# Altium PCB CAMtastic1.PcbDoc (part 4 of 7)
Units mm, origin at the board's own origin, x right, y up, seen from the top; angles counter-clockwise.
Board outline 150.22 x 135.24 mm, 5 copper layers (Top Layer, Layer 1, Mid-Layer 1, Layer 2, Bottom Layer), stack 0.461 mm thick; 0 components, 362 nets, 2885 pads, 0 vias.
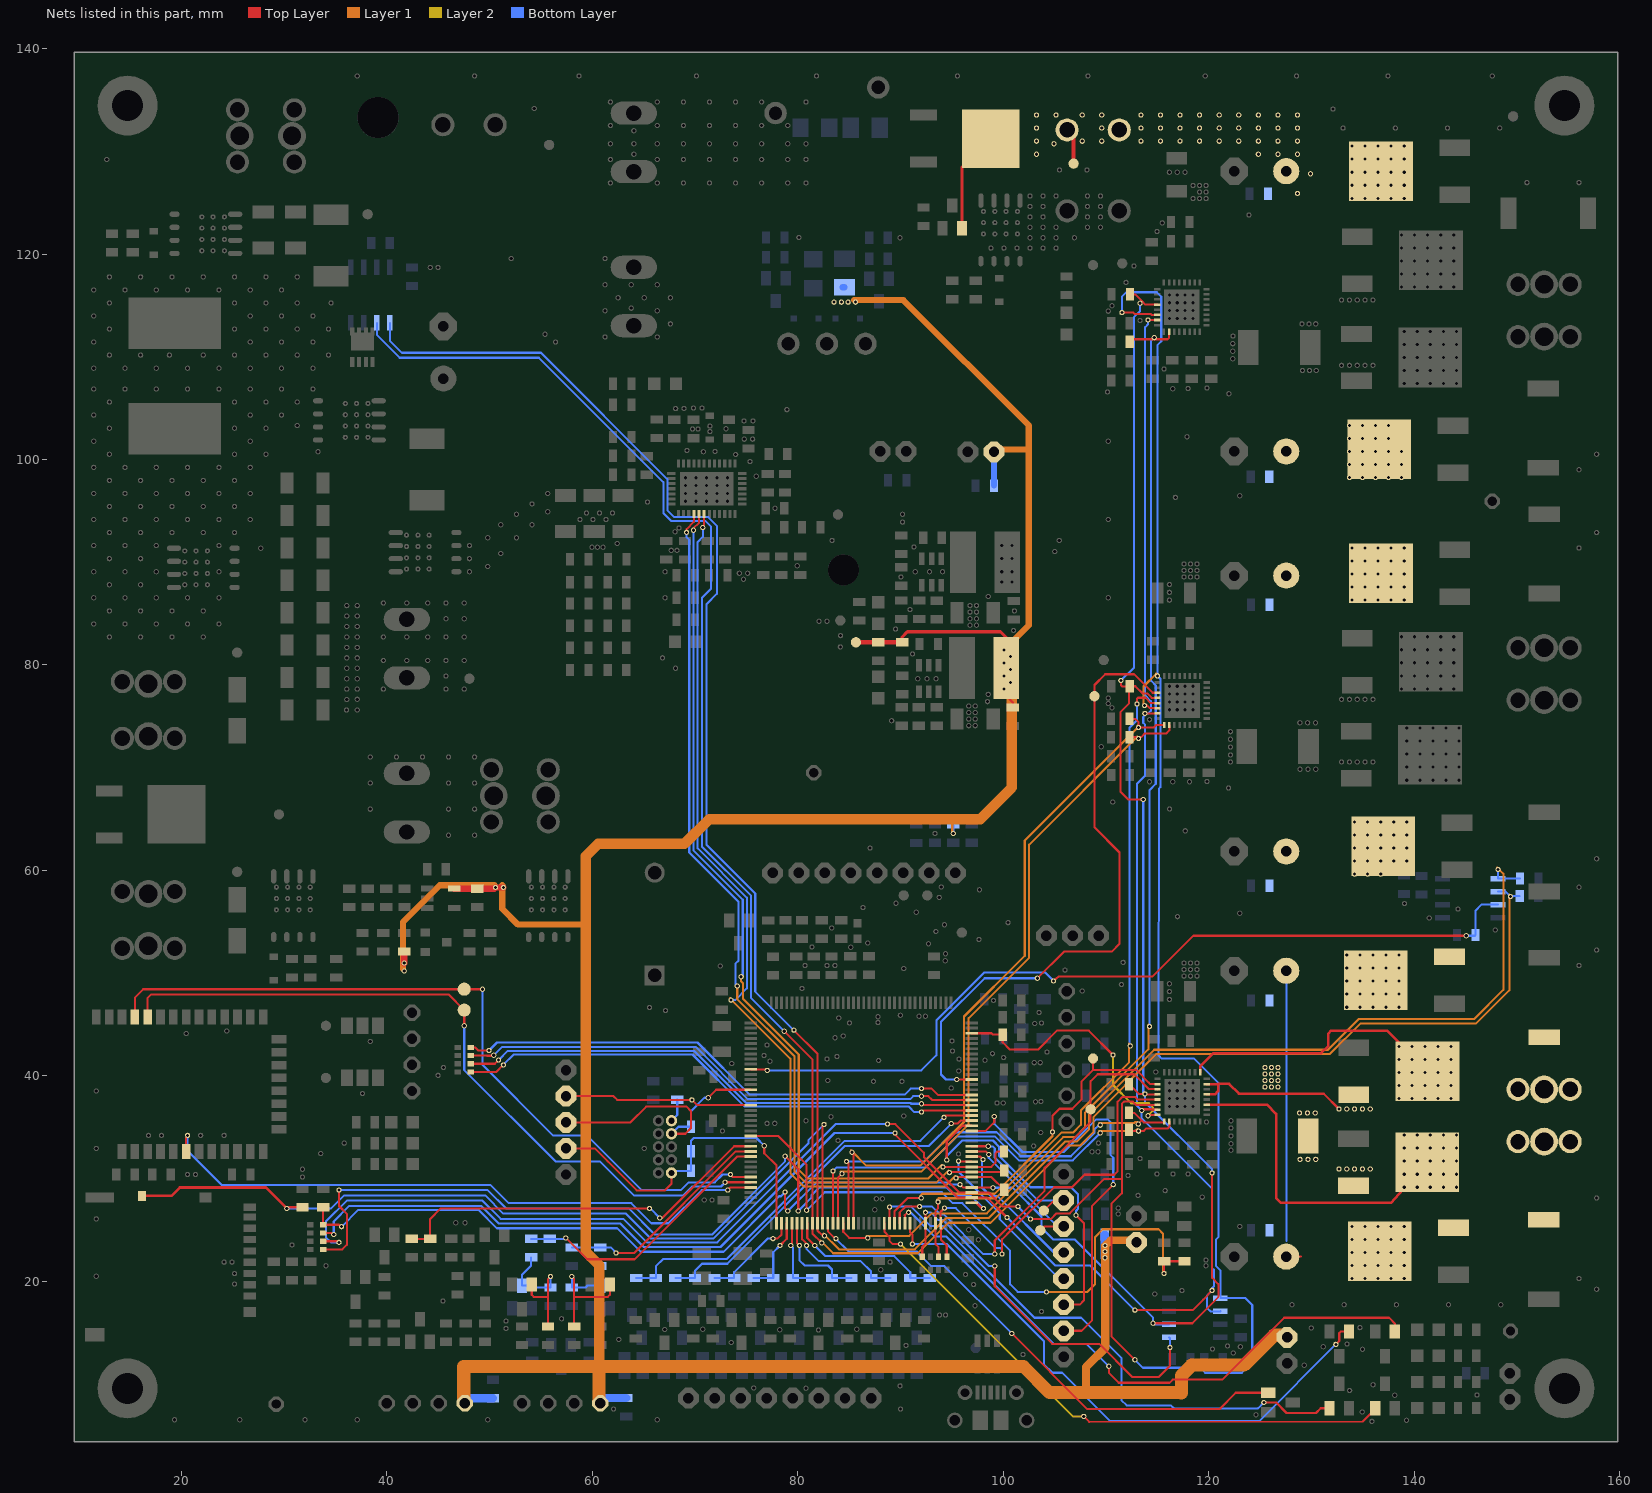
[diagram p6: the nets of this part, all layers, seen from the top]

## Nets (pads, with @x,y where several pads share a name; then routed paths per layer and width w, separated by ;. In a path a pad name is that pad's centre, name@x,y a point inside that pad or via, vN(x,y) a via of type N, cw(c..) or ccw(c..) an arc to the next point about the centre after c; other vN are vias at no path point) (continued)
$Net7: pad.1@119.805,37.203 pad.1@139.018,29.159 pad.1@139.018,30.429 pad.1@139.018,31.699 pad.1@139.018,32.969 pad.1@139.018,34.239 pad.1@140.288,29.159 pad.1@140.288,30.429 pad.1@140.288,31.699 pad.1@140.288,32.969 pad.1@140.288,34.239 pad.1@141.273,31.603 pad.1@141.558,29.159 pad.1@141.558,30.429 pad.1@141.558,31.699 pad.1@141.558,32.969 pad.1@141.558,34.239 pad.1@142.828,29.159 pad.1@142.828,30.429 pad.1@142.828,31.699 pad.1@142.828,32.969 pad.1@142.828,34.239 pad.1@143.821,25.216 pad.1@144.098,29.159 pad.1@144.098,30.429 pad.1@144.098,31.699 pad.1@144.098,32.969 pad.1@144.098,34.239 pad.1@150.093,33.604 pad.1@152.584,25.994 pad.1@152.633,33.604 pad.1@155.173,33.604 | length 32
  Top Layer w0.254: pad.1@119.805,37.203 125.64,37.203 126.547,36.297 126.547,28.092 127.004,27.635 137.748,27.635 pad.1@141.273,31.603
$Net8: pad.1@119.155,40.353 pad.1@138.51,37.795 pad.1@138.51,39.065 pad.1@138.51,40.335 pad.1@138.51,41.605 pad.1@138.51,42.875 pad.1@139.78,37.795 pad.1@139.78,39.065 pad.1@139.78,40.335 pad.1@139.78,41.605 pad.1@139.78,42.875 pad.1@141.05,37.795 pad.1@141.05,39.065 pad.1@141.05,40.335 pad.1@141.05,41.605 pad.1@141.05,42.875 pad.1@141.294,40.468 pad.1@142.32,37.795 pad.1@142.32,39.065 pad.1@142.32,40.335 pad.1@142.32,41.605 pad.1@142.32,42.875 pad.1@143.59,37.795 pad.1@143.59,39.065 pad.1@143.59,40.335 pad.1@143.59,41.605 pad.1@143.59,42.875 pad.1@143.435,51.606 pad.1@150.093,38.684 pad.1@152.633,38.684 pad.1@152.635,43.765 pad.1@155.173,38.684 | length 26.5
  Top Layer w0.254: pad.1@119.155,40.353 119.155,40.891 120.479,42.215 130.941,42.215 131.627,42.901 131.627,44.12 131.906,44.399 137.362,44.399 pad.1@141.294,40.468 pad.1@141.304,40.479
$Net9: pad.1@119.805,38.203 pad.1@119.805,39.203 pad.1@128.833,36.398 pad.1@128.884,31.877 pad.1@129.595,36.398 pad.1@129.646,31.877 pad.1@129.676,34.169 pad.1@130.357,36.398 pad.1@130.408,31.877 pad.1@132.668,30.937 pad.1@132.668,36.779 pad.1@133.43,30.937 pad.1@133.43,36.779 pad.1@134.093,29.318 pad.1@134.114,38.183 pad.1@134.192,30.937 pad.1@134.192,36.779 pad.1@134.954,30.937 pad.1@134.954,36.779 pad.1@135.716,30.937 pad.1@135.716,36.779 | length 15.8
  Top Layer w0.203: 131.17,38.278 pad.1@132.668,36.779
  Top Layer w0.254: pad.1@119.805,38.203 120.608,38.203 120.911,38.506 120.911,39.218 121.975,39.218 122.915,38.278 131.17,38.278 ; pad.1@119.805,39.203 120.896,39.203
  Top Layer w0.305: 120.896,39.203 120.911,39.218
$Net10: pad.1@95.967,122.522 pad.1@98.772,131.242 pad.1@103.23,129.718 pad.1@103.23,130.988 pad.1@103.23,132.258 pad.1@103.23,133.528 pad.1@104.923,130.734 pad.1@105.135,133.528 pad.1@106.201,132.08 pad.1@106.839,128.803 pad.1@107.675,130.988 pad.1@107.675,133.528 pad.1@109.58,130.988 pad.1@109.58,132.258 pad.1@109.58,133.528 pad.1@111.281,132.08 pad.1@113.39,130.988 pad.1@113.39,132.258 pad.1@113.39,133.528 pad.1@115.295,130.988 pad.1@115.295,132.258 pad.1@115.295,133.528 pad.1@117.2,130.988 pad.1@117.2,132.258 pad.1@117.2,133.528 pad.1@119.105,130.988 pad.1@119.105,132.258 pad.1@119.105,133.528 pad.1@121.01,130.988 pad.1@121.01,132.258 pad.1@121.01,133.528 pad.1@122.915,130.988 pad.1@122.915,132.258 pad.1@122.915,133.528 pad.1@124.82,129.718 pad.1@124.82,130.988 pad.1@124.82,132.258 pad.1@124.82,133.528 pad.1@125.77,125.882 pad.1@125.455,38.913 pad.1@125.455,39.548 pad.1@125.455,40.183 pad.1@125.455,40.818 pad.1@125.872,98.323 pad.1@125.897,24.968 pad.1@125.897,47.346 pad.1@125.897,58.496 pad.1@125.897,85.877 pad.1@126.09,38.913 pad.1@126.09,39.548 pad.1@126.09,40.183 pad.1@126.09,40.818 pad.1@126.725,38.913 pad.1@126.725,39.548 pad.1@126.725,40.183 pad.1@126.725,40.818 pad.1@126.725,129.718 pad.1@126.725,130.988 pad.1@126.725,132.258 pad.1@126.725,133.528 pad.1@127.54,22.403 pad.1@127.54,50.241 pad.1@127.54,61.849 pad.1@127.54,88.697 pad.1@127.54,100.787 pad.1@127.54,128.067 pad.1@128.63,125.908 pad.1@128.63,129.718 pad.1@128.63,130.988 pad.1@128.63,132.258 pad.1@128.63,133.528 pad.1@129.9,127.813 pad.1@133.43,46.685 pad.1@133.43,47.955 pad.1@133.43,49.225 pad.1@133.43,50.495 pad.1@133.43,51.765 pad.1@133.684,98.247 pad.1@133.684,99.517 pad.1@133.684,100.787 pad.1@133.684,102.057 pad.1@133.684,103.327 pad.1@133.938,20.269 pad.1@133.938,21.539 pad.1@133.938,22.809 pad.1@133.938,24.079 pad.1@133.938,25.349 pad.1@133.938,86.309 pad.1@133.938,87.579 pad.1@133.938,88.849 pad.1@133.938,90.119 pad.1@133.938,91.389 pad.1@133.938,125.425 pad.1@133.938,126.695 pad.1@133.938,127.965 pad.1@133.938,129.235 pad.1@133.938,130.505 pad.1@134.7,46.685 pad.1@134.7,47.955 pad.1@134.7,49.225 pad.1@134.7,50.495 pad.1@134.7,51.765 pad.1@134.192,59.639 pad.1@134.192,60.909 pad.1@134.192,62.179 pad.1@134.192,63.449 pad.1@134.192,64.719 pad.1@134.954,98.247 pad.1@134.954,99.517 pad.1@134.954,100.787 pad.1@134.954,102.057 pad.1@134.954,103.327 pad.1@135.97,46.685 pad.1@135.97,47.955 pad.1@135.97,49.225 pad.1@135.97,50.495 pad.1@135.97,51.765 pad.1@135.208,20.269 pad.1@135.208,21.539 pad.1@135.208,22.809 pad.1@135.208,24.079 pad.1@135.208,25.349 pad.1@135.208,86.309 pad.1@135.208,87.579 pad.1@135.208,88.849 pad.1@135.208,90.119 pad.1@135.208,91.389 pad.1@135.208,125.425 pad.1@135.208,126.695 pad.1@135.208,127.965 pad.1@135.208,129.235 pad.1@135.208,130.505 pad.1@135.462,59.639 pad.1@135.462,60.909 pad.1@135.462,62.179 pad.1@135.462,63.449 pad.1@135.462,64.719 pad.1@136.224,98.247 pad.1@136.224,99.517 pad.1@136.224,100.787 pad.1@136.224,102.057 pad.1@136.224,103.327 pad.1@136.255,49.321 pad.1@136.478,20.269 pad.1@136.478,21.539 pad.1@136.478,22.809 pad.1@136.478,24.079 pad.1@136.478,25.349 pad.1@136.478,86.309 pad.1@136.478,87.579 pad.1@136.478,88.849 pad.1@136.478,90.119 pad.1@136.478,91.389 pad.1@136.478,125.425 pad.1@136.478,126.695 pad.1@136.478,127.965 pad.1@136.478,129.235 pad.1@136.478,130.505 pad.1@136.591,100.99 pad.1@136.641,22.931 pad.1@136.732,59.639 pad.1@136.732,60.909 pad.1@136.732,62.179 pad.1@136.732,63.449 pad.1@136.732,64.719 pad.1@136.763,88.913 pad.1@136.763,128.067 pad.1@136.972,62.345 pad.1@137.24,46.685 pad.1@137.24,47.955 pad.1@137.24,49.225 pad.1@137.24,50.495 pad.1@137.24,51.765 pad.1@137.494,98.247 pad.1@137.494,99.517 pad.1@137.494,100.787 pad.1@137.494,102.057 pad.1@137.494,103.327 pad.1@137.748,20.269 pad.1@137.748,21.539 pad.1@137.748,22.809 pad.1@137.748,24.079 pad.1@137.748,25.349 pad.1@137.748,86.309 pad.1@137.748,87.579 pad.1@137.748,88.849 pad.1@137.748,90.119 pad.1@137.748,91.389 pad.1@137.748,125.425 pad.1@137.748,126.695 pad.1@137.748,127.965 pad.1@137.748,129.235 pad.1@137.748,130.505 pad.1@138.002,60.909 pad.1@138.002,62.179 pad.1@138.002,63.449 pad.1@138.002,64.719 pad.1@138.51,46.685 pad.1@138.51,47.955 pad.1@138.51,49.225 pad.1@138.51,50.495 pad.1@138.51,51.765 pad.1@138.764,98.247 pad.1@138.764,99.517 pad.1@138.764,100.787 pad.1@139.018,20.269 pad.1@139.018,21.539 pad.1@139.018,22.809 pad.1@139.018,24.079 pad.1@139.018,25.349 pad.1@139.018,86.309 pad.1@139.018,87.579 pad.1@139.018,88.849 pad.1@139.018,90.119 pad.1@139.018,91.389 pad.1@139.018,125.425 pad.1@139.018,126.695 pad.1@139.018,127.965 pad.1@139.018,129.235 pad.1@139.018,130.505 pad.1@139.272,60.909 pad.1@139.272,62.179 pad.1@139.272,63.449 pad.1@139.272,64.719 | length 41.2
  Top Layer w0.203: pad.1@127.54,22.403 128.982,22.423
  Top Layer w0.305: pad.1@95.967,122.522 95.967,128.402 98.772,131.208 pad.1@98.772,131.242
  Top Layer w0.406: pad.1@106.201,132.08 106.839,131.442 pad.1@106.839,128.803
  Bottom Layer w0.203: pad.1@127.54,50.241 127.56,50.221 127.56,23.947
$Net11: pad.1@90.911,25.654 pad.1@91.139,23.622 pad.1@132.363,13.868 pad.1@133.646,15.119 | length 57.1
  Top Layer w0.203: pad.1@90.911,25.654 90.911,25.603 90.911,24.79 91.139,24.562 pad.1@91.139,23.622 ; pad.1@132.363,13.868 132.694,14.199 132.694,14.961 132.852,15.119 pad.1@133.646,15.119
  Bottom Layer w0.203: pad.1@91.139,23.622 94.517,23.622 103.941,14.199 103.941,11.938 104.779,11.1 105.719,11.1 110.418,6.401 124.896,6.401 pad.1@132.363,13.868
$Net12: pad.1@88.911,25.654 pad.1@88.929,27.229 pad.1@125.353,8.204 pad.1@131.746,7.639 | length 56
  Top Layer w0.203: pad.1@88.911,25.654 88.929,25.756 pad.1@88.929,27.229 ; pad.1@125.353,8.204 126.547,8.204 127.563,7.188 130.433,7.188 130.89,7.645 131.74,7.645 pad.1@131.746,7.639 131.595,7.639 131.576,7.62 pad.1@131.601,7.62
  Bottom Layer w0.203: pad.1@88.929,27.229 88.98,27.28 91.038,27.28 92.943,25.375 94.111,25.375 103.026,16.459 107.573,16.459 111.485,12.548 111.485,8.433 111.993,7.925 116.311,7.925 116.615,7.62 124.794,7.645 pad.1@125.353,8.204
$Net13: pad.1@92.098,22.393 pad.1@92.409,26.721 pad.1@92.411,25.654 pad.1@99.166,21.488 pad.1@116.124,14.554 pad.1@116.209,13.564 | length 39.3
  Top Layer w0.203: pad.1@92.098,22.393 92.104,22.399 92.104,23.343 92.411,23.649 pad.1@92.411,25.654 92.411,26.595 pad.1@92.409,26.721 ; pad.1@99.166,21.488 99.166,19.507 104.754,13.919 109.326,13.919 112.551,10.693 115.142,10.693 116.209,11.76 pad.1@116.209,13.564
  Bottom Layer w0.203: pad.1@92.409,26.721 92.917,26.721 93.679,25.959 94.136,25.959 98.607,21.488 pad.1@99.166,21.488 ; pad.1@116.124,14.554 116.209,14.478 pad.1@116.209,13.564
$Net14: pad.1@33.783,25.508 pad.1@33.783,27.218 pad.1@35.581,25.324 pad.1@78.761,28.694 pad.1@79.015,26.848 pad.1@95.787,29.413 pad.1@96.905,29.148 pad.1@98.988,29.108 pad.1@111.434,78.486 pad.1@112.235,39.198 pad.1@112.311,77.914 pad.1@112.336,116.078 pad.1@113.313,115.214 pad.1@113.618,66.904 pad.1@113.771,38.252 pad.1@114.98,115.083 pad.1@114.575,15.926 pad.1@115.005,38.203 pad.1@115.005,76.792 pad.1@116.124,15.824 pad.1@120.324,30.556 | length 219
  Top Layer w0.203: pad.1@33.783,27.218 pad.1@33.783,25.508 35.314,25.508 35.498,25.324 pad.1@35.581,25.324 ; pad.1@78.761,28.694 78.761,27.102 pad.1@79.015,26.848 ; pad.1@95.787,29.413 96.052,29.148 pad.1@96.905,29.148 98.948,29.148 pad.1@98.988,29.108 ; pad.1@111.434,78.486 111.434,78.054 111.586,77.902 pad.1@112.29,77.902 ; pad.1@112.235,39.198 112.247,39.167 113.161,38.252 pad.1@113.771,38.252 113.821,38.202 pad.1@115.005,38.203 ; pad.1@112.336,116.078 112.831,116.078 113.504,115.405 ; pad.1@113.313,115.214 113.504,115.405 ; pad.1@113.618,66.904 112.145,66.904 111.408,67.64 111.408,75.438 112.247,76.276 112.247,77.876 pad.1@112.29,77.902 ; pad.1@114.575,15.926 118.385,15.926 120.925,18.466 120.925,19.736 120.324,20.337 pad.1@120.324,30.556 ; pad.1@114.98,115.083 113.826,115.083 113.504,115.405 ; pad.1@115.005,76.792 114.448,76.792 113.999,77.241 113.542,77.241 112.856,77.927 112.324,77.927 pad.1@112.311,77.914 pad.1@112.29,77.902
  Bottom Layer w0.203: pad.1@35.581,25.324 37.22,26.963 48.904,26.963 50.696,25.171 62.403,25.171 64.689,22.885 72.766,22.885 78.164,28.284 78.35,28.284 pad.1@78.761,28.694 ; pad.1@79.015,26.848 81.783,29.616 94.619,29.616 94.822,29.413 pad.1@95.787,29.413 ; pad.1@98.988,29.108 100.918,29.108 103.712,26.314 103.712,25.222 104.855,24.079 106.963,24.079 114.575,16.468 pad.1@114.575,15.926 114.657,15.926 114.759,15.824 pad.1@116.124,15.824 ; pad.1@111.434,78.486 112.704,79.705 112.704,113.843 113.313,114.452 pad.1@113.313,115.214 ; pad.1@113.618,66.904 113.618,38.405 pad.1@113.771,38.252 113.771,37.465 120.324,30.912 pad.1@120.324,30.556
$Net15: pad.1@75.417,34.148 pad.1@80.852,26.924 pad.1@104.195,18.974 pad.1@115.65,20.777 pad.1@115.65,21.96 pad.1@117.631,21.96 | length 64.6
  Top Layer w0.203: pad.1@75.417,34.148 78.073,34.148 80.852,31.369 pad.1@80.852,26.924 ; pad.1@115.65,20.777 pad.1@115.65,21.96 pad.1@117.631,21.96
  Layer 1 w0.203: pad.1@104.195,18.974 104.203,18.982 108.186,18.982 108.914,19.71 108.914,24.308 109.676,25.07 115.112,25.07 115.544,24.638 pad.1@115.544,20.98
  Bottom Layer w0.203: pad.1@80.852,26.924 82.605,28.677 94.009,28.677 95.076,27.61 96.016,27.61 100.664,22.962 100.664,19.71 101.401,18.974 pad.1@104.195,18.974
$Net16: pad.1@33.783,24.708 pad.1@34.819,24.562 pad.1@89.463,34.442 pad.1@96.905,28.148 pad.1@100.359,26.213 pad.1@112.797,17.196 pad.1@113.466,36.627 pad.1@113.771,75.286 pad.1@114.075,113.589 pad.1@114.98,113.583 pad.1@115.005,36.703 pad.1@115.005,75.292 pad.1@120.324,19.126 pad.1@121.125,17.094 | length 208.8
  Top Layer w0.203: pad.1@33.783,24.708 34.59,24.708 34.736,24.562 pad.1@34.819,24.562 ; pad.1@89.463,34.442 89.463,34.265 95.579,28.148 pad.1@96.905,28.148 98.424,28.148 pad.1@100.359,26.213 ; pad.1@112.797,17.196 118.432,17.196 119.46,18.224 pad.1@120.324,19.126 ; pad.1@113.466,36.627 113.593,36.754 114.431,36.754 114.482,36.703 pad.1@115.005,36.703 ; pad.1@113.771,75.286 114.99,75.286 pad.1@115.005,75.292 ; pad.1@114.075,113.589 114.081,113.583 pad.1@114.98,113.583
  Bottom Layer w0.203: pad.1@34.819,24.562 34.819,25.832 36.343,27.356 49.158,27.356 50.885,25.629 62.708,25.629 64.994,23.343 72.461,23.343 83.561,34.442 pad.1@89.463,34.442 ; pad.1@100.359,26.213 100.385,26.213 105.058,21.539 108.453,21.539 pad.1@112.797,17.196 ; pad.1@114.075,113.589 114.075,113.157 113.796,112.878 113.796,77.038 114.355,76.479 114.355,75.54 114.101,75.286 pad.1@113.771,75.286 113.771,75.108 113.618,74.955 113.618,74.371 113.771,74.219 113.771,69.19 113.009,68.428 113.009,37.084 pad.1@113.466,36.627 113.466,35.865 120.324,29.007 120.324,21.285 120.502,21.107 120.502,19.533 120.324,19.355 pad.1@120.324,19.126 119.841,18.644 119.841,17.399 120.171,17.069 121.086,17.069 pad.1@121.125,17.094
$Net17: pad.1@96.905,34.648 pad.1@99.115,36.043 pad.1@105.871,15.189 pad.1@110.697,29.413 | length 41.1
  Top Layer w0.203: pad.1@96.905,34.648 98.279,34.648 99.115,35.484 pad.1@99.115,36.043 ; pad.1@105.871,15.189 107.624,15.189 108.64,16.205 108.64,27.356 pad.1@110.697,29.413
  Bottom Layer w0.203: pad.1@99.115,36.043 99.115,35.331 101.858,32.588 105.871,32.588 109.046,35.763 110.164,35.763 110.418,35.509 110.418,32.309 110.697,32.029 pad.1@110.697,29.413
$Net18: pad.1@94.492,31.801 pad.1@96.905,35.148 pad.1@105.871,17.729 pad.1@107.065,26.441 | length 34.2
  Top Layer w0.203: pad.1@94.492,31.801 94.492,33.604 96.036,35.148 pad.1@96.905,35.148 ; pad.1@105.871,17.729 107.421,17.729 107.852,18.161 107.852,25.654 pad.1@107.065,26.441
  Bottom Layer w0.203: pad.1@94.492,31.801 94.492,32.207 95.991,33.706 98.988,33.706 99.572,33.122 99.572,32.233 102.645,29.159 106.582,29.159 107.268,28.473 107.268,27.051 107.065,26.848 pad.1@107.065,26.441
$Net19: pad.1@41.677,50.216 pad.1@41.677,50.978 pad.1@41.677,52.11 pad.1@46.539,58.228 pad.1@47.578,8.136 pad.1@48.789,58.228 pad.1@50.321,8.625 pad.1@50.567,58.344 pad.1@51.329,58.344 pad.1@60.761,8.136 pad.1@63.301,8.647 pad.1@83.519,115.316 pad.1@84.23,115.316 pad.1@84.535,116.761 pad.1@84.891,115.316 pad.1@85.602,115.316 pad.1@85.653,82.207 pad.1@87.837,82.205 pad.1@90.149,82.205 pad.1@95.127,63.602 pad.1@95.127,64.502 pad.1@99.088,97.46 pad.1@99.088,100.754 pad.1@100.055,77.648 pad.1@100.055,78.918 pad.1@100.055,80.188 pad.1@100.055,81.458 pad.1@100.69,78.283 pad.1@100.69,79.553 pad.1@100.69,80.823 pad.1@100.274,79.705 pad.1@100.918,75.855 pad.1@109.873,24.562 pad.1@109.884,22.301 pad.1@109.884,22.911 pad.1@109.884,23.495 pad.1@112.958,23.8 pad.1@127.616,14.554 | length 336.9
  Top Layer w0.203: pad.1@100.274,79.705 100.274,78.918 100.274,76.997 100.918,76.352 pad.1@100.918,75.855
  Top Layer w0.305: pad.1@90.149,82.205 90.149,82.728 90.657,83.236 99.724,83.236 100.283,82.677 100.283,80.823 100.283,79.715 pad.1@100.274,79.705
  Top Layer w0.406: pad.1@85.653,82.207 87.835,82.207 pad.1@87.837,82.205 pad.1@90.149,82.205
  Top Layer w0.61: pad.1@41.677,50.978 pad.1@41.677,52.11 ; pad.1@46.539,58.228 pad.1@48.789,58.228 50.45,58.228 pad.1@50.567,58.344 pad.1@51.329,58.344
  Layer 1 w0.203: 93.852,64.999 95.021,65.126 95.021,64.999 pad.1@95.021,63.805 ; pad.1@99.948,77.851 100.075,77.724 pad.1@100.294,77.724
  Layer 1 w0.61: pad.1@41.57,50.419 41.57,54.991 45.126,58.547 pad.1@50.46,58.547 ; pad.1@51.222,58.547 51.222,56.261 52.746,54.737 59.334,54.737 ; pad.1@85.496,115.519 90.262,115.519 102.463,103.318 102.463,100.965 ; pad.1@98.982,100.957 98.99,100.965 102.463,100.965 ; pad.1@100.583,81.026 100.583,81.982 102.463,83.861 102.463,100.965
  Layer 1 w0.762: pad.1@109.931,23.494 110.44,24.003 pad.1@112.851,24.003
  Layer 1 w0.813: 108.051,9.169 108.051,11.659 109.931,13.539 109.931,22.911 pad.1@109.931,23.494
  Layer 1 w1.016: 60.654,11.709 60.654,21.565 59.334,22.885 59.334,54.737 59.334,61.366 60.578,62.611 68.96,62.611 71.348,64.999 93.852,64.999 95.021,64.999 97.764,64.999 100.837,68.072 100.837,77.181 pad.1@100.294,77.724
  Layer 1 w1.27: pad.1@47.472,8.339 47.472,11.709 60.654,11.709 ; pad.1@60.654,8.339 60.654,11.709 ; 100.29,81.57 100.294,80.823 100.294,78.918 pad.1@100.294,77.724 ; pad.1@127.51,14.757 126.364,14.757 123.443,11.836 118.338,11.836 117.322,10.82 117.322,9.141 117.299,9.119 117.248,9.169 108.051,9.169 104.495,9.169 101.955,11.709 60.654,11.709
  Bottom Layer w0.203: pad.1@95.127,63.602 pad.1@95.127,64.502 ; pad.1@95.127,64.502 95.127,64.516 95.025,64.618 pad.1@95.127,64.502
  Bottom Layer w0.61: pad.1@84.335,116.761 pad.1@84.535,116.761 ; pad.1@99.088,97.46 pad.1@99.088,100.754
  Bottom Layer w0.813: pad.1@47.578,8.136 47.589,8.625 pad.1@50.321,8.625 ; pad.1@60.761,8.136 60.772,8.647 pad.1@63.301,8.647 ; pad.1@109.873,24.562 109.873,23.481 pad.1@109.884,22.911 pad.1@109.884,22.301
$Net21: pad.1@90.411,25.654 pad.1@90.784,26.721 pad.1@110.265,11.735 pad.1@138.091,15.119 | length 59.6
  Top Layer w0.203: pad.1@90.411,25.654 90.411,26.221 90.403,26.441 90.682,26.721 pad.1@90.784,26.721 ; pad.1@110.265,11.735 110.265,11.1 111.231,10.135 116.184,10.135 116.488,10.439 121.314,10.439 127.334,16.459 137.545,16.459 138.104,15.9 138.104,15.132 pad.1@138.091,15.119 pad.1@138.002,15.24
  Bottom Layer w0.203: pad.1@90.784,26.721 90.961,26.721 93.273,24.384 94.416,24.384 104.881,13.919 108.081,13.919 pad.1@110.265,11.735
$Net22: pad.1@88.411,25.654 pad.1@89.996,23.622 pad.1@107.827,6.858 pad.1@136.191,7.639 | length 57.1
  Top Layer w0.203: pad.1@88.411,25.654 88.411,24.852 88.904,24.359 88.904,23.952 89.234,23.622 pad.1@89.996,23.622 ; pad.1@107.827,6.858 108.36,6.325 134.954,6.35 136.173,7.569 136.173,7.62 136.191,7.638 pad.1@136.191,7.639
  Layer 2 w0.203: pad.1@89.996,23.622 106.786,6.833 107.802,6.833 pad.1@107.827,6.858
$Net23: pad.1@83.411,25.654 pad.1@83.418,30.734 pad.1@109.427,34.442 pad.1@112.235,34.773 pad.1@113.161,34.62 pad.1@116.155,35.553 | length 43
  Top Layer w0.203: pad.1@83.411,25.654 83.418,25.661 pad.1@83.418,30.734 ; pad.1@112.235,34.773 112.387,34.62 pad.1@113.161,34.62 113.644,34.62 113.923,34.9 116.006,34.9 116.155,35.049 pad.1@116.155,35.553
  Layer 1 w0.203: pad.1@109.321,34.646 112.75,34.646 pad.1@113.055,34.823
  Bottom Layer w0.203: pad.1@83.418,30.734 83.773,31.09 92.46,31.09 95.483,34.112 99.166,34.112 101.502,31.775 106.76,31.775 pad.1@109.427,34.442
$Net24: pad.1@84.738,31.674 pad.1@84.911,25.654 pad.1@109.427,35.204 pad.1@112.235,36.398 pad.1@113.132,35.302 pad.1@115.655,35.553 | length 42.5
  Top Layer w0.203: pad.1@84.738,31.674 84.911,31.552 pad.1@84.911,25.654 ; pad.1@112.235,36.398 112.755,36.398 113.479,35.674 ; pad.1@113.132,35.302 113.132,35.328 113.479,35.674 ; pad.1@115.655,35.553 115.655,35.507 115.632,35.484 113.669,35.484 113.479,35.674
  Layer 1 w0.203: pad.1@109.321,35.408 112.75,35.408 112.862,35.52 113.011,35.52 pad.1@113.025,35.506
  Bottom Layer w0.203: pad.1@84.738,31.674 92.282,31.674 95.127,34.519 99.343,34.519 101.68,32.182 106.557,32.182 108.868,34.493 108.868,34.798 109.275,35.204 pad.1@109.427,35.204
$Net25: pad.1@96.905,44.148 pad.1@99.942,44.018 pad.1@110.672,42.037 pad.1@114.075,36.119 pad.1@115.005,36.203 | length 26.3
  Top Layer w0.203: pad.1@96.905,44.148 98.858,44.148 98.988,44.018 pad.1@99.942,44.018 99.942,43.267 100.639,42.57 103.382,42.57 105.211,44.399 108.31,44.399 pad.1@110.672,42.037 ; pad.1@114.075,36.119 114.16,36.203 pad.1@115.005,36.203
  Layer 2 w0.203: pad.1@110.672,42.037 110.672,39.116 112.45,37.338 114.152,37.338 114.558,36.932 114.558,36.601 pad.1@114.075,36.119
$Net27: pad.1@89.411,25.654 pad.1@92.003,28.118 pad.1@104.779,34.544 pad.1@108.729,41.694 pad.1@115.005,39.203 | length 36.4
  Top Layer w0.203: pad.1@89.411,25.654 89.411,26.847 90.682,28.118 pad.1@92.003,28.118 ; pad.1@104.779,34.544 104.779,36.119 105.465,36.805 106.709,36.805 107.624,37.719 107.624,39.472 108.741,40.589 ; pad.1@108.729,41.694 108.741,41.681 108.741,40.589 ; pad.1@115.005,39.203 114.279,39.218 114.152,39.345 112.932,40.589 108.741,40.589
  Layer 1 w0.203: pad.1@91.896,28.321 92.1,28.524 99.148,28.524 104.779,34.156 pad.1@104.779,34.544
$Net28: pad.1@82.911,25.654 pad.1@83.697,24.155 pad.1@100.817,14.935 pad.1@125.781,9.154 | length 51.5
  Top Layer w0.203: pad.1@82.911,25.654 82.911,24.865 83.621,24.155 pad.1@83.697,24.155 ; pad.1@100.817,14.935 108.183,7.569 121.035,7.569 122.62,9.154 pad.1@125.781,9.154
  Bottom Layer w0.203: pad.1@83.697,24.155 84.942,22.911 91.546,22.911 92.968,21.488 94.263,21.488 pad.1@100.817,14.935
$Net29: pad.1@89.911,25.654 pad.1@91.85,27.28 pad.1@99.166,22.657 pad.1@108.5,36.754 pad.1@115.005,38.703 | length 40.8
  Top Layer w0.203: pad.1@89.911,25.654 89.911,26.712 90.479,27.28 pad.1@91.85,27.28 ; pad.1@99.166,22.657 99.166,23.978 104.017,28.829 104.017,31.064 108.5,35.547 pad.1@108.5,36.754 ; pad.1@108.284,36.754 pad.1@108.5,36.754 ; pad.1@115.005,38.703 114.999,38.71 114.177,38.71 112.729,40.157 109.173,40.157 108.5,39.484 pad.1@108.5,36.754
  Bottom Layer w0.203: pad.1@91.85,27.28 93.07,27.28 93.832,26.518 94.187,26.518 98.048,22.657 pad.1@99.166,22.657
$Net30: pad.1@93.911,25.654 pad.1@94.263,27.127 pad.1@94.498,22.393 pad.1@99.877,22.657 pad.1@115.005,37.703 | length 39.2
  Top Layer w0.203: pad.1@94.263,27.127 93.886,26.749 pad.1@93.911,25.654 93.911,24.076 94.492,23.495 94.492,22.399 pad.1@94.498,22.393 ; pad.1@99.877,22.657 99.877,24.102 100.73,24.955 104.957,29.159 106.684,29.159 107.903,30.378 110.799,30.378 111.129,30.709 111.129,37.49 111.586,37.948 112.831,37.948 113.085,37.694 114.996,37.694 pad.1@115.005,37.703
  Bottom Layer w0.203: pad.1@94.263,27.127 95.381,27.127 99.267,23.241 99.724,23.241 99.877,23.089 pad.1@99.877,22.657
$Net31: pad.1@33.783,23.108 pad.1@35.327,28.88 pad.1@78.761,32.182 pad.1@80.031,26.848 pad.1@96.905,27.648 pad.1@98.065,27.102 | length 84
  Top Layer w0.203: pad.1@33.783,23.108 35.651,23.108 36.089,23.546 36.089,26.574 35.327,27.336 pad.1@35.327,28.88 ; pad.1@78.761,32.182 80.031,30.912 pad.1@80.031,26.848
  Top Layer w0.254: pad.1@96.905,27.648 97.375,27.648 97.921,27.102 pad.1@98.065,27.102
  Bottom Layer w0.203: pad.1@35.327,28.88 49.805,28.88 51.583,27.102 63.521,27.102 66.061,24.562 71.649,24.562 78.761,31.674 pad.1@78.761,32.182 ; pad.1@80.031,26.848 81.315,28.132 81.315,28.357 82.092,29.134 94.509,29.134 95.271,28.372 96.795,28.372 pad.1@98.065,27.102
$Net32: pad.1@70.743,93.37 pad.1@70.877,94.703 pad.1@73.486,47.371 pad.1@95.406,30.048 pad.1@96.905,30.148 pad.1@100.088,28.91 | length 92.2
  Top Layer w0.203: pad.1@70.743,93.37 70.877,93.504 pad.1@70.877,94.703 ; pad.1@95.406,30.048 95.507,30.148 pad.1@96.905,30.148 96.98,30.148 96.981,30.15 98.848,30.15 pad.1@100.088,28.91
  Layer 1 w0.203: pad.1@73.38,47.574 79.273,41.681 79.273,30.531 80.568,29.235 94.284,29.235 pad.1@95.3,30.251
  Bottom Layer w0.203: pad.1@70.743,93.37 70.743,92.481 70.235,91.973 70.235,62.154 75.036,57.353 75.036,48.514 73.893,47.371 pad.1@73.486,47.371
$Net33: pad.1@69.168,92.913 pad.1@69.877,94.703 pad.1@74.096,48.743 pad.1@94.746,30.582 pad.1@96.905,30.648 pad.1@100.088,30.789 | length 90.2
  Top Layer w0.203: pad.1@69.168,92.913 69.166,93.215 69.879,93.929 pad.1@69.877,94.703 ; pad.1@94.746,30.582 94.813,30.648 pad.1@96.905,30.648 99.947,30.648 pad.1@100.088,30.789
  Layer 1 w0.203: pad.1@74.096,48.743 74.096,47.468 79.679,41.885 79.679,30.683 80.746,29.616 93.471,29.616 pad.1@94.64,30.785
  Bottom Layer w0.203: pad.1@69.168,92.913 69.168,92.431 69.422,92.177 69.422,61.747 74.223,56.947 74.223,51.206 73.918,50.902 73.918,48.92 pad.1@74.096,48.743
$Net34: pad.1@69.829,93.116 pad.1@70.377,94.703 pad.1@74.477,49.657 pad.1@94.111,31.14 pad.1@96.905,31.148 pad.1@100.063,32.643 | length 90.4
  Top Layer w0.203: pad.1@69.829,93.116 69.829,93.294 70.387,93.853 70.387,94.692 pad.1@70.377,94.703 ; pad.1@94.111,31.14 94.119,31.148 pad.1@96.905,31.148 98.818,31.148 99.216,31.547 99.216,32.436 99.424,32.643 pad.1@100.063,32.643
  Layer 1 w0.203: pad.1@74.477,49.657 74.477,49.183 74.65,49.01 74.65,47.523 80.085,42.088 80.085,30.861 80.949,29.997 92.658,29.997 pad.1@94.005,31.344
  Bottom Layer w0.203: pad.1@69.829,93.116 69.829,61.951 74.629,57.15 74.629,49.809 pad.1@74.477,49.657
$Net35: pad.1@95.635,31.699 pad.1@96.905,31.648 pad.1@105.871,20.269 | length 17.2
  Top Layer w0.203: pad.1@95.635,31.699 95.686,31.648 pad.1@96.905,31.648
  Bottom Layer w0.203: pad.1@95.635,31.699 95.635,30.658 99.648,26.645 99.648,26.06 105.439,20.269 pad.1@105.871,20.269
$Net36: pad.1@96.905,32.148 pad.1@98.023,31.852 pad.1@105.871,22.809 | length 14.6
  Top Layer w0.203: pad.1@96.905,32.148 97.726,32.148 pad.1@98.023,31.852
  Bottom Layer w0.203: pad.1@98.023,31.852 97.921,31.75 97.921,29.134 98.734,28.321 99.42,28.321 104.881,22.86 105.846,22.86 pad.1@105.871,22.809
$Net37: pad.1@96.905,32.648 pad.1@98.581,32.36 pad.1@103.598,24.968 pad.1@105.871,25.349 | length 14.6
  Top Layer w0.203: pad.1@96.905,32.648 98.293,32.648 pad.1@98.581,32.36 ; pad.1@103.598,24.968 103.979,25.349 pad.1@105.871,25.349
  Bottom Layer w0.203: pad.1@98.581,32.36 98.581,32.029 105.262,25.349 pad.1@105.871,25.349
$Net38: pad.1@96.905,33.148 pad.1@98.531,33.147 pad.1@103.941,26.886 pad.1@105.871,27.889 | length 14
  Top Layer w0.203: pad.1@96.905,33.148 98.453,33.148 pad.1@98.531,33.147 ; pad.1@103.941,26.886 104.944,27.889 pad.1@105.871,27.889
  Bottom Layer w0.203: pad.1@98.531,33.147 98.962,33.147 99.166,32.944 99.166,32.055 103.331,27.889 pad.1@105.871,27.889
$Net39: pad.1@33.783,23.908 pad.1@35.327,23.8 pad.1@88.726,35.306 pad.1@96.905,28.648 pad.1@101.426,27.28 pad.1@102.645,26.06 pad.1@111.535,114.3 pad.1@112.797,12.37 pad.1@113.745,76.048 pad.1@114.98,114.083 pad.1@114.99,78.943 pad.1@115.005,37.203 pad.1@115.005,75.792 pad.1@121.125,18.364 | length 262.8
  Top Layer w0.203: pad.1@33.783,23.908 35.136,23.908 35.244,23.8 pad.1@35.327,23.8 ; pad.1@88.726,35.306 89.488,35.306 92.257,32.537 92.257,32.106 95.714,28.648 pad.1@96.905,28.648 98.585,28.648 99.953,27.28 pad.1@101.426,27.28 ; pad.1@102.645,26.06 104.614,26.06 105.173,26.619 106.472,26.619 109.825,29.972 111.535,29.972 ; pad.1@111.535,114.3 112.653,114.3 112.805,114.148 114.355,114.148 114.419,114.083 pad.1@114.98,114.083 ; pad.1@112.797,12.37 110.511,14.656 110.511,27.55 111.535,28.575 111.535,29.972 ; pad.1@113.745,76.048 114.025,76.048 114.279,75.794 114.483,75.792 pad.1@115.005,75.792 ; pad.1@115.005,37.203 114.99,37.188 114.99,37.186 112.907,37.186 112.602,37.49 111.739,37.49 111.535,37.287 111.535,29.972
  Layer 1 w0.203: pad.1@113.639,76.251 113.639,77.902 pad.1@114.883,79.146
  Bottom Layer w0.203: pad.1@35.327,23.8 34.565,23.8 34.057,24.308 34.057,25.832 36.089,27.864 49.297,27.864 51.075,26.086 63.013,26.086 65.299,23.8 72.157,23.8 83.663,35.306 pad.1@88.726,35.306 ; pad.1@101.426,27.28 pad.1@102.645,26.06 ; pad.1@111.535,114.3 111.535,115.849 111.967,116.281 114.939,116.281 115.371,115.849 115.371,111.506 114.99,111.125 pad.1@114.99,78.943 115.295,78.638 115.295,68.123 115.168,67.996 115.117,41.986 115.422,41.681 118.571,41.681 120.933,39.319 120.958,24.341 120.679,24.063 120.679,21.514 121.125,21.069 pad.1@121.125,18.364 123.566,18.364 124.227,17.704 124.227,12.116 123.211,11.1 119.655,11.1 119.162,11.592 113.574,11.592 pad.1@112.797,12.37
$Net40: pad.1@93.411,25.654 pad.1@93.654,27.737 pad.1@93.698,22.393 pad.1@112.348,42.926 pad.1@113.009,76.2 pad.1@115.005,76.292 | length 68.8
  Top Layer w0.203: pad.1@93.654,27.737 93.654,27.102 93.411,26.859 pad.1@93.411,25.654 93.411,23.611 93.705,23.317 93.705,22.399 pad.1@93.698,22.393 ; pad.1@113.009,76.2 113.009,76.708 113.11,76.81 113.847,76.81 114.364,76.292 pad.1@115.005,76.292
  Layer 1 w0.203: pad.1@93.547,27.94 93.7,28.092 99.262,28.092 105.642,34.472 106.785,34.472 107.543,35.23 107.543,36.627 112.242,41.326 pad.1@112.242,43.129
  Bottom Layer w0.203: pad.1@112.348,42.926 112.297,42.977 112.297,73.914 113.009,74.625 pad.1@113.009,76.2
$Net41: pad.1@84.411,25.654 pad.1@86.796,24.232 pad.1@112.311,111.455 pad.1@114.228,44.806 pad.1@114.685,111.862 pad.1@116.13,112.433 | length 114.1
  Top Layer w0.203: pad.1@84.411,25.654 84.411,24.813 84.992,24.232 pad.1@86.796,24.232 ; pad.1@112.311,111.455 112.399,111.709 pad.1@114.685,111.709 ; pad.1@114.685,111.862 pad.1@114.685,111.709 ; pad.1@116.13,112.433 116.13,111.859 115.98,111.709 pad.1@114.685,111.709
  Layer 1 w0.203: pad.1@86.689,24.435 90.855,24.435 93.036,26.616 98.396,26.616 105.816,34.036 106.984,34.036 107.949,35.001 107.949,36.424 114.121,42.596 pad.1@114.121,45.009
  Bottom Layer w0.203: pad.1@114.228,44.806 114.228,67.818 114.837,68.428 114.837,78.003 114.38,78.461 114.38,111.557 pad.1@114.685,111.862
$Net42: pad.1@40.28,113.302 pad.1@79.608,44.45 pad.1@81.911,25.654 pad.1@82.579,24.435 pad.1@148.147,59.207 pad.1@148.162,60.096 pad.1@150.285,59.21 | length 210.5
  Top Layer w0.203: pad.1@79.608,44.45 81.911,42.147 pad.1@81.911,25.654 81.911,24.926 82.402,24.435 pad.1@82.579,24.435
  Layer 1 w0.203: pad.1@82.473,24.638 83.997,23.114 91.388,23.114 94.436,26.162 98.577,26.162 106.044,33.63 107.187,33.63 108.356,34.798 108.356,36.22 114.68,42.545 131.597,42.545 134.594,45.542 145.821,45.542 148.665,48.387 148.665,59.69 pad.1@148.056,60.3
  Bottom Layer w0.203: pad.1@40.28,113.302 40.28,111.557 41.446,110.391 54.993,110.391 67.289,98.095 67.289,95.047 67.949,94.386 71.276,94.386 72.115,93.548 72.115,86.919 71.099,85.903 71.099,62.509 75.848,57.76 75.848,48.209 pad.1@79.608,44.45 ; pad.1@148.162,60.096 148.162,59.223 pad.1@148.147,59.207 150.282,59.207 pad.1@150.285,59.21
$Net43: pad.1@39.01,113.302 pad.1@78.668,44.348 pad.1@81.411,25.654 pad.1@82.325,23.749 pad.1@148.147,57.937 pad.1@149.356,57.455 pad.1@150.26,57.508 | length 209.3
  Top Layer w0.203: pad.1@78.668,44.348 81.411,41.605 pad.1@81.411,25.654 81.411,24.664 pad.1@82.325,23.749
  Layer 1 w0.203: pad.1@82.219,23.952 83.438,22.733 91.668,22.733 94.64,25.705 98.754,25.705 106.261,33.211 107.455,33.211 108.762,34.519 108.762,35.992 114.909,42.139 131.8,42.139 134.772,45.11 146.024,45.11 149.25,48.336 pad.1@149.25,57.658
  Bottom Layer w0.203: pad.1@39.01,113.302 39.01,112.141 41.245,109.906 54.792,109.906 66.908,97.79 66.908,94.793 67.695,94.005 71.022,94.005 71.53,93.497 71.53,87.401 70.667,86.538 70.667,62.306 75.442,57.531 75.442,47.574 pad.1@78.668,44.348 ; pad.1@148.147,57.937 148.899,57.937 pad.1@149.331,57.506 ; pad.1@150.26,57.508 150.257,57.506 pad.1@149.331,57.506 ; pad.1@149.331,57.506 pad.1@149.356,57.455 149.585,57.48 149.361,57.503 pad.1@149.331,57.506
$Net44: pad.1@80.911,25.654 pad.1@81.64,23.495 pad.1@90.936,20.331 pad.1@92.841,20.331 | length 15.3
  Top Layer w0.203: pad.1@80.911,25.654 80.911,24.224 pad.1@81.64,23.495
  Bottom Layer w0.203: pad.1@81.64,23.495 82.681,22.454 89.387,22.454 90.936,20.904 pad.1@90.936,20.331 pad.1@92.841,20.331
$Net45: pad.1@80.411,25.654 pad.1@80.852,23.495 pad.1@87.126,20.331 pad.1@89.031,20.331 | length 12.4
  Top Layer w0.203: pad.1@80.411,25.654 80.411,24.089 80.852,23.647 pad.1@80.852,23.495
  Bottom Layer w0.203: pad.1@80.852,23.495 80.852,23.139 82.021,21.971 86.11,21.971 87.126,20.955 pad.1@87.126,20.331 pad.1@89.031,20.331
$Net46: pad.1@79.911,25.654 pad.1@80.141,23.495 pad.1@83.316,20.331 pad.1@85.221,20.331 | length 10
  Top Layer w0.203: pad.1@79.911,25.654 79.911,23.725 pad.1@80.141,23.495
  Bottom Layer w0.203: pad.1@80.141,23.495 80.141,22.073 80.674,21.539 82.935,21.539 83.316,21.158 pad.1@83.316,20.331 pad.1@85.221,20.331
$Net47: pad.1@79.303,23.495 pad.1@79.411,25.654 pad.1@79.506,20.331 pad.1@81.411,20.331 | length 7.4
  Top Layer w0.203: pad.1@79.303,23.495 79.411,23.603 pad.1@79.411,25.654
  Bottom Layer w0.203: pad.1@79.303,23.495 79.506,23.292 pad.1@79.506,20.331 pad.1@81.411,20.331
$Net48: pad.1@75.696,20.331 pad.1@77.601,20.331 pad.1@78.261,23.495 pad.1@78.911,25.654 | length 7.8
  Top Layer w0.203: pad.1@78.261,23.495 78.911,24.144 pad.1@78.911,25.654
  Bottom Layer w0.203: pad.1@75.696,20.331 pad.1@77.601,20.331 77.601,22.835 pad.1@78.261,23.495
$Net49: pad.1@71.886,20.331 pad.1@73.791,20.331 pad.1@77.576,24.155 pad.1@78.411,25.654 | length 9.7
  Top Layer w0.203: pad.1@77.576,24.155 78.007,24.155 78.411,24.559 pad.1@78.411,25.654
  Bottom Layer w0.203: pad.1@71.886,20.331 pad.1@73.791,20.331 73.791,20.904 77.042,24.155 pad.1@77.576,24.155
$Net50: pad.1@57.425,32.944 pad.1@67.695,30.556 pad.1@69.589,30.759 pad.1@69.589,32.664 pad.1@76.729,33.198 pad.1@77.911,25.654 | length 33.8
  Top Layer w0.203: pad.1@57.425,32.944 60.219,32.944 61.489,31.674 64.308,28.854 67.06,28.854 67.695,29.489 pad.1@67.695,30.556 ; pad.1@76.729,33.198 76.729,32.47 77.911,31.288 pad.1@77.911,25.654
  Bottom Layer w0.203: pad.1@67.695,30.556 67.898,30.759 pad.1@69.589,30.759 pad.1@69.589,32.664 69.589,33.678 69.871,33.96 75.967,33.96 pad.1@76.729,33.198
$Net51: pad.1@16.141,28.318 pad.1@30.247,27.102 pad.1@31.771,27.218 pad.1@82.411,25.654 pad.1@82.554,35.281 | length 85.9
  Top Layer w0.203: pad.1@30.247,27.102 30.329,27.102 30.445,27.218 pad.1@31.771,27.218 ; pad.1@82.411,25.654 82.411,35.137 pad.1@82.554,35.281
  Top Layer w0.254: pad.1@16.141,28.318 19.016,28.318 19.833,29.134 28.215,29.134 pad.1@30.247,27.102
  Bottom Layer w0.203: pad.1@30.247,27.102 34.565,27.102 35.835,28.372 49.551,28.372 51.329,26.594 63.267,26.594 65.705,24.155 71.75,24.155 77.999,30.404 78.004,30.404 81.024,33.424 81.024,33.751 pad.1@82.554,35.281
$Net52: pad.1@85.272,32.563 pad.1@85.411,25.654 pad.1@112.286,74.752 pad.1@113.161,73.914 pad.1@115.655,74.142 | length 70.1
  Top Layer w0.203: pad.1@85.272,32.563 85.411,32.424 pad.1@85.411,25.654 ; pad.1@112.286,74.752 112.831,74.752 113.161,74.422 pad.1@113.161,73.914 114.634,73.914 114.863,74.142 pad.1@115.655,74.142
  Layer 1 w0.203: pad.1@85.165,32.766 86.664,31.267 91.922,31.267 96.168,35.514 96.168,45.782 102.083,51.696 102.083,62.917 113.055,73.889 pad.1@113.055,74.117
$Net53: pad.1@83.911,25.654 pad.1@84.281,30.48 pad.1@112.286,72.974 pad.1@113.161,72.847 pad.1@116.155,74.142 | length 68.7
  Top Layer w0.203: pad.1@83.911,25.654 83.911,30.088 83.9,30.099 pad.1@84.281,30.48 ; pad.1@112.286,72.974 pad.1@113.186,72.974 ; pad.1@113.161,72.847 113.161,72.949 pad.1@113.186,72.974 ; pad.1@116.155,74.142 116.155,73.632 115.853,73.33 113.771,73.33 113.415,72.974 pad.1@113.186,72.974
  Layer 1 w0.203: pad.1@84.175,30.683 92.023,30.683 96.622,35.281 96.622,45.611 102.514,51.503 102.514,62.509 pad.1@113.055,73.05
$Net54: pad.1@48.144,42.78 pad.1@49.928,42.473 pad.1@92.028,38.76 pad.1@96.905,38.148 | length 51.8
  Top Layer w0.203: pad.1@48.144,42.78 48.57,42.78 48.877,42.473 pad.1@49.928,42.473 ; pad.1@92.028,38.76 93.019,38.76 93.631,38.148 pad.1@96.905,38.148
  Bottom Layer w0.203: pad.1@49.928,42.473 50.711,43.256 70.226,43.256 75.306,38.176 90.403,38.176 90.987,38.76 pad.1@92.028,38.76
$Net55: pad.1@48.144,41.98 pad.1@50.395,42.006 pad.1@92.028,38.024 pad.1@96.905,37.648 | length 51.5
  Top Layer w0.203: pad.1@48.144,41.98 49.702,41.98 49.717,41.965 50.138,41.965 50.153,41.98 50.369,41.98 pad.1@50.395,42.006 ; pad.1@92.028,38.024 92.689,38.024 93.064,37.648 pad.1@96.905,37.648
  Bottom Layer w0.203: pad.1@50.395,42.006 51.213,42.824 70.047,42.824 75.127,37.744 90.936,37.744 91.215,38.024 pad.1@92.028,38.024
$Net56: pad.1@48.144,41.18 pad.1@50.861,41.539 pad.1@92.028,37.287 pad.1@96.905,37.148 | length 51.5
  Top Layer w0.203: pad.1@48.144,41.18 50.503,41.18 pad.1@50.861,41.539 ; pad.1@92.028,37.287 92.167,37.148 pad.1@96.905,37.148
  Bottom Layer w0.203: pad.1@50.861,41.539 51.766,42.443 69.889,42.443 74.97,37.363 90.956,37.363 91.033,37.287 pad.1@92.028,37.287
$Net57: pad.1@48.144,40.38 pad.1@51.329,41.072 pad.1@92.028,36.474 pad.1@96.905,36.648 | length 51.9
  Top Layer w0.203: pad.1@48.144,40.38 50.637,40.38 pad.1@51.329,41.072 ; pad.1@92.028,36.474 92.202,36.648 pad.1@96.905,36.648
  Bottom Layer w0.203: pad.1@51.329,41.072 52.345,42.088 69.742,42.088 74.822,37.008 90.809,37.008 91.342,36.474 pad.1@92.028,36.474
$Net58: pad.1@64.266,20.331 pad.1@66.171,20.331 pad.1@94.213,35.966 pad.1@96.905,36.148 | length 39.9
  Top Layer w0.203: pad.1@94.213,35.966 94.395,36.148 pad.1@96.905,36.148
  Bottom Layer w0.203: pad.1@64.266,20.331 pad.1@66.171,20.331 66.171,21.463 66.882,22.174 73.071,22.174 84.577,33.68 91.927,33.68 pad.1@94.213,35.966
$Net59: pad.1@68.076,20.331 pad.1@69.981,20.331 pad.1@94.924,35.357 pad.1@96.905,35.648 | length 35.6
  Top Layer w0.203: pad.1@94.924,35.357 95.533,35.357 95.825,35.648 pad.1@96.905,35.648
  Bottom Layer w0.203: pad.1@68.076,20.331 pad.1@69.981,20.331 69.981,21.031 70.667,21.717 73.122,21.717 84.577,33.172 92.739,33.172 pad.1@94.924,35.357
$Net60: pad.1@95.457,39.649 pad.1@96.905,39.648 pad.1@103.306,49.505 pad.1@108.868,76.962 pad.1@115.005,77.292 | length 62.3
  Top Layer w0.203: pad.1@95.457,39.649 pad.1@95.457,39.649 pad.1@96.905,39.648 ; pad.1@103.306,49.505 105.897,52.095 110.545,52.095 111.307,52.857 111.307,61.747 108.868,64.186 pad.1@108.868,76.962 108.868,78.054 109.91,79.096 112.729,79.096 114.532,77.292 pad.1@115.005,77.292
  Bottom Layer w0.203: pad.1@95.457,39.649 94.416,39.649 93.933,40.132 93.933,45.263 98.175,49.505 pad.1@103.306,49.505
$Net61: pad.1@75.417,40.648 pad.1@77.017,40.538 pad.1@104.881,49.251 pad.1@145.063,53.645 pad.1@145.966,53.721 pad.1@148.147,56.667 | length 83.5
  Top Layer w0.203: pad.1@75.417,40.648 75.425,40.64 76.915,40.64 pad.1@77.017,40.538 ; pad.1@104.881,49.251 105.389,49.682 114.533,49.682 118.495,53.645 pad.1@145.063,53.645
  Bottom Layer w0.203: pad.1@77.017,40.538 92.003,40.538 93.476,42.012 93.476,45.39 98.15,50.063 104.068,50.063 pad.1@104.881,49.251 ; pad.1@145.063,53.645 145.927,53.645 pad.1@145.966,53.721 145.966,56.097 146.537,56.667 pad.1@148.147,56.667
$Net62: pad.1@57.425,35.484 pad.1@67.695,34.366 pad.1@69.589,35.052 pad.1@71.276,37.871 pad.1@75.417,38.648 | length 27.2
  Top Layer w0.203: pad.1@57.425,35.484 63.707,35.484 65.231,37.008 69.168,37.008 69.6,36.576 69.6,34.925 69.041,34.366 pad.1@67.695,34.366 ; pad.1@71.276,37.871 72.053,38.648 pad.1@75.417,38.648
  Bottom Layer w0.203: pad.1@67.695,34.366 68.381,35.052 pad.1@69.589,35.052 69.589,36.565 70.895,37.871 pad.1@71.276,37.871
$Net63: pad.1@57.425,38.024 pad.1@67.695,35.636 pad.1@68.254,37.683 pad.1@69.676,37.668 pad.1@75.417,37.148 | length 22.1
  Top Layer w0.203: pad.1@57.425,38.024 62.047,38.024 62.403,37.668 pad.1@69.676,37.668 70.196,37.148 pad.1@75.417,37.148
  Bottom Layer w0.203: pad.1@67.695,35.636 68.254,36.195 pad.1@68.254,37.683 68.268,37.668 pad.1@69.676,37.668
$Net64: pad.1@15.456,45.738 pad.1@47.519,48.438 pad.1@49.297,48.438 pad.1@73.427,30.404 pad.1@75.417,30.148 | length 75.3
  Top Layer w0.203: pad.1@15.456,45.738 15.456,47.617 16.277,48.438 pad.1@47.519,48.438 pad.1@49.297,48.438 ; pad.1@73.427,30.404 73.682,30.148 pad.1@75.417,30.148
  Bottom Layer w0.203: pad.1@49.297,48.438 49.297,41.072 56.155,34.214 59.457,34.214 64.791,28.88 68.601,28.88 69.363,29.642 71.903,29.642 72.665,30.404 pad.1@73.427,30.404
$Net65: pad.1@16.706,45.738 pad.1@47.519,44.882 pad.1@47.519,46.406 pad.1@72.919,29.642 pad.1@75.417,29.648 | length 72.8
  Top Layer w0.203: pad.1@16.706,45.738 16.706,47.597 17.039,47.93 45.995,47.93 pad.1@47.519,46.406 pad.1@47.519,44.882 ; pad.1@72.919,29.642 72.925,29.648 pad.1@75.417,29.648
  Bottom Layer w0.203: pad.1@47.519,44.882 47.519,40.564 56.409,31.674 60.727,31.674 64.029,28.372 68.855,28.372 69.718,29.235 72.512,29.235 pad.1@72.919,29.642
$Net66: pad.1@20.455,32.631 pad.1@20.595,34.214 pad.1@73.173,28.88 pad.1@75.417,29.148 | length 62.3
  Top Layer w0.203: pad.1@20.455,32.631 20.455,33.992 20.595,34.131 pad.1@20.595,34.214 ; pad.1@73.173,28.88 73.441,29.148 pad.1@75.417,29.148
  Bottom Layer w0.203: pad.1@20.595,34.214 20.595,32.69 23.897,29.388 50.059,29.388 51.837,27.61 63.775,27.61 65.73,25.654 67.407,25.654 70.633,28.88 pad.1@73.173,28.88
$Net67: pad.1@42.422,24.141 pad.1@44.2,24.141 pad.1@65.553,27.102 pad.1@66.552,26.162 pad.1@75.417,33.148 | length 38.6
  Top Layer w0.203: pad.1@42.422,24.141 pad.1@44.2,24.141 44.2,26.069 45.233,27.102 pad.1@65.553,27.102 ; pad.1@66.552,26.162 66.806,26.162 73.792,33.148 pad.1@75.417,33.148
  Bottom Layer w0.203: pad.1@65.553,27.102 65.612,27.102 pad.1@66.552,26.162
$Net68: pad.1@57.992,19.391 pad.1@57.992,20.472 pad.1@58.221,15.607 pad.1@60.761,19.591 pad.1@60.761,21.503 pad.1@61.711,19.691 | length 15.4
  Top Layer w0.203: pad.1@57.992,20.472 58.221,20.244 58.221,18.491 ; pad.1@58.221,15.607 58.221,18.491 ; pad.1@61.711,19.691 61.711,18.705 61.497,18.491 58.221,18.491
  Bottom Layer w0.203: pad.1@57.992,20.472 pad.1@57.992,19.391 59.324,19.391 59.524,19.591 pad.1@60.761,19.591
  Bottom Layer w0.254: pad.1@60.761,19.591 pad.1@60.761,21.503
$Net69: pad.1@53.141,19.591 pad.1@54.03,22.341 pad.1@54.091,19.691 pad.1@55.681,15.607 pad.1@55.909,19.391 pad.1@55.909,20.472 | length 14.7
  Top Layer w0.203: pad.1@54.091,19.691 54.091,18.684 54.284,18.491 55.681,18.491 ; pad.1@55.681,15.607 55.681,18.491 ; pad.1@55.909,20.472 55.681,20.244 55.681,18.491
  Bottom Layer w0.203: pad.1@54.03,22.341 54.03,21.539 53.141,20.65 pad.1@53.141,19.591 54.352,19.591 54.552,19.391 pad.1@55.909,19.391 pad.1@55.909,20.472
$Net70: pad.1@54.03,24.141 pad.1@55.859,24.141 pad.1@57.408,24.232 pad.1@75.417,32.148 | length 26.4
  Top Layer w0.203: pad.1@57.408,24.232 59.491,22.149 64.114,22.149 74.113,32.148 pad.1@75.417,32.148
  Bottom Layer w0.203: pad.1@54.03,24.141 pad.1@55.859,24.141 57.317,24.141 pad.1@57.408,24.232
$Net71: pad.1@57.992,23.303 pad.1@60.761,23.303 pad.1@62.31,22.758 pad.1@75.417,32.648 | length 21.7
  Top Layer w0.203: pad.1@62.31,22.758 64.063,22.758 73.953,32.648 pad.1@75.417,32.648
  Bottom Layer w0.203: pad.1@57.992,23.303 pad.1@60.761,23.303 61.766,23.303 pad.1@62.31,22.758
